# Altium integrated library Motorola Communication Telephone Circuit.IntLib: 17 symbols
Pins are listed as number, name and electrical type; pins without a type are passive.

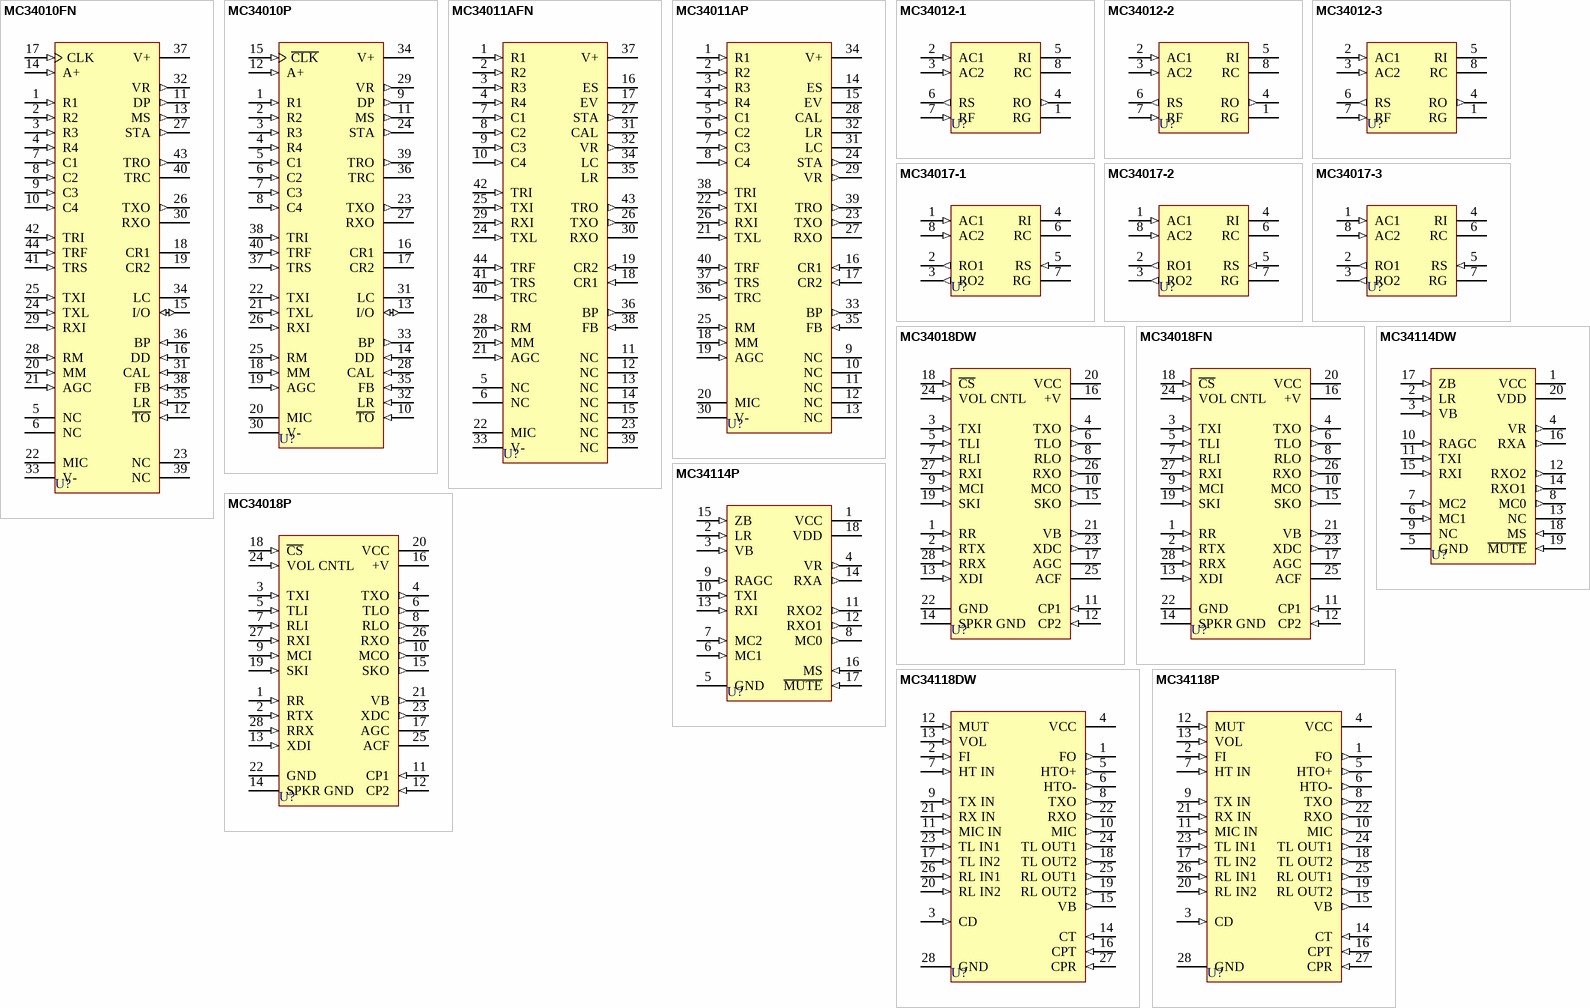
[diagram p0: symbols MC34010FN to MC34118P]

## MC34010FN
designator U?
Electronic Telephone Circuit
footprint 777-02_N (Leaded Chip Carrier, 44-Leads, Body 16.6x16.6mm, Pitch 1.27mm, IPC Medium Density)
footprint 777-02_L (Leaded Chip Carrier, 44-Leads, Body 16.6x16.6mm, Pitch 1.27mm, IPC High Density)
footprint 777-02_M (Leaded Chip Carrier, 44-Leads, Body 16.6x16.6mm, Pitch 1.27mm, IPC Low Density)
3D model MC34010-777-02 (44-Pin Plastic Leaded Chip Carrier 1.27 mm Pitch)
pins: 1 R1 (in), 2 R2 (in), 3 R3 (in), 4 R4 (in), 5 NC, 6 NC, 7 C1 (in), 8 C2 (in), 9 C3 (in), 10 C4 (in), 11 DP (out), 12 ~{TO} (in), 13 MS (out), 14 A+ (in), 15 I/O (io), 16 DD (in), 17 CLK (in), 18 CR1, 19 CR2, 20 MM (in), 21 AGC (in), 22 MIC (power), 23 NC, 24 TXL (in), 25 TXI (in), 26 TXO (out), 27 STA (out), 28 RM (in), 29 RXI (in), 30 RXO (oc), 31 CAL (in), 32 VR (out), 33 V- (power), 34 LC, 35 LR (in), 36 BP (in), 37 V+ (power), 38 FB (in), 39 NC, 40 TRC, 41 TRS (in), 42 TRI (in), 43 TRO (out), 44 TRF (in)

## MC34010P
designator U?
Electronic Telephone Circuit
footprint 711-03 (DIP; 40 Leads; Row Spacing 15.24 mm; Pitch 2.54 mm)
3D model 711-03 (DIP; 40 Leads; Row Spacing 15.24 mm; Pitch 2.54 mm)
pins: 1 R1 (in), 2 R2 (in), 3 R3 (in), 4 R4 (in), 5 C1 (in), 6 C2 (in), 7 C3 (in), 8 C4 (in), 9 DP (out), 10 ~{TO} (in), 11 MS (out), 12 A+ (in), 13 I/O (io), 14 DD (in), 15 ~{CLK} (in), 16 CR1, 17 CR2, 18 MM (in), 19 AGC (in), 20 MIC (power), 21 TXL (in), 22 TXI (in), 23 TXO (out), 24 STA (out), 25 RM (in), 26 RXI (in), 27 RXO (oc), 28 CAL (in), 29 VR (out), 30 V- (power), 31 LC, 32 LR (in), 33 BP (out), 34 V+ (power), 35 FB (in), 36 TRC, 37 TRS (in), 38 TRI (in), 39 TRO (out), 40 TRF (in)

## MC34011AFN
designator U?
Electronic Telephone Circuit
footprint 777-02_N (Leaded Chip Carrier, 44-Leads, Body 16.6x16.6mm, Pitch 1.27mm, IPC Medium Density)
footprint 777-02_L (Leaded Chip Carrier, 44-Leads, Body 16.6x16.6mm, Pitch 1.27mm, IPC High Density)
footprint 777-02_M (Leaded Chip Carrier, 44-Leads, Body 16.6x16.6mm, Pitch 1.27mm, IPC Low Density)
3D model MC34011A-777-02 (44-Pin Plastic Leaded Chip Carrier 1.27 mm Pitch)
pins: 1 R1 (in), 2 R2 (in), 3 R3 (in), 4 R4 (in), 5 NC, 6 NC, 7 C1 (in), 8 C2 (in), 9 C3 (in), 10 C4 (in), 11 NC, 12 NC, 13 NC, 14 NC, 15 NC, 16 ES, 17 EV, 18 CR1 (in), 19 CR2 (in), 20 MM (in), 21 AGC (in), 22 MIC (power), 23 NC, 24 TXL (in), 25 TXI (in), 26 TXO (out), 27 STA (out), 28 RM (in), 29 RXI (in), 30 RXO (oc), 31 CAL, 32 VR (out), 33 V- (power), 34 LC, 35 LR, 36 BP (out), 37 V+ (power), 38 FB (in), 39 NC, 40 TRC (in), 41 TRS (in), 42 TRI (in), 43 TRO (out), 44 TRF (in)

## MC34011AP
designator U?
Electronic Telephone Circuit
footprint 711-03 (DIP; 40 Leads; Row Spacing 15.24 mm; Pitch 2.54 mm)
3D model 711-03 (DIP; 40 Leads; Row Spacing 15.24 mm; Pitch 2.54 mm)
pins: 1 R1 (in), 2 R2 (in), 3 R3 (in), 4 R4 (in), 5 C1 (in), 6 C2 (in), 7 C3 (in), 8 C4 (in), 9 NC, 10 NC, 11 NC, 12 NC, 13 NC, 14 ES, 15 EV, 16 CR1 (in), 17 CR2 (in), 18 MM (in), 19 AGC (in), 20 MIC (power), 21 TXL (in), 22 TXI (in), 23 TXO (out), 24 STA (out), 25 RM (in), 26 RXI (in), 27 RXO (oc), 28 CAL, 29 VR (out), 30 V- (power), 31 LC, 32 LR, 33 BP (out), 34 V+ (power), 35 FB (in), 36 TRC (in), 37 TRS (in), 38 TRI (in), 39 TRO (out), 40 TRF (in)

## MC34012-1
designator U?
Telephone Tone Ringer
footprint 626-05 (DIP; 8 Leads; Row Spacing 7.62 mm; Pitch 2.54 mm)
3D model 626-05 (DIP; 8 Leads; Row Spacing 7.62 mm; Pitch 2.54 mm)
pins: 1 RG (power), 2 AC1 (in), 3 AC2 (in), 4 RO (out), 5 RI (power), 6 RS (out), 7 RF (in), 8 RC

## MC34012-2
designator U?
Telephone Tone Ringer
footprint 626-05 (DIP; 8 Leads; Row Spacing 7.62 mm; Pitch 2.54 mm)
3D model 626-05 (DIP; 8 Leads; Row Spacing 7.62 mm; Pitch 2.54 mm)
pins: 1 RG (power), 2 AC1 (in), 3 AC2 (in), 4 RO (out), 5 RI (power), 6 RS (out), 7 RF (in), 8 RC

## MC34012-3
designator U?
Telephone Tone Ringer
footprint 626-05 (DIP; 8 Leads; Row Spacing 7.62 mm; Pitch 2.54 mm)
3D model 626-05 (DIP; 8 Leads; Row Spacing 7.62 mm; Pitch 2.54 mm)
pins: 1 RG (power), 2 AC1 (in), 3 AC2 (in), 4 RO (out), 5 RI (power), 6 RS (out), 7 RF (in), 8 RC

## MC34017-1
designator U?
Telephone Tone Ringer
footprint 626-04 (DIP; 8 Leads; Row Spacing 7.62 mm; Pitch 2.54 mm)
3D model 626-05 (DIP; 8 Leads; Row Spacing 7.62 mm; Pitch 2.54 mm)
pins: 1 AC1 (in), 2 RO1 (out), 3 RO2 (out), 4 RI (power), 5 RS (in), 6 RC, 7 RG (power), 8 AC2 (in)

## MC34017-2
designator U?
Telephone Tone Ringer
footprint 626-04 (DIP; 8 Leads; Row Spacing 7.62 mm; Pitch 2.54 mm)
3D model 626-05 (DIP; 8 Leads; Row Spacing 7.62 mm; Pitch 2.54 mm)
pins: 1 AC1 (in), 2 RO1 (out), 3 RO2 (out), 4 RI (power), 5 RS (in), 6 RC, 7 RG (power), 8 AC2 (in)

## MC34017-3
designator U?
Telephone Tone Ringer
footprint 626-04 (DIP; 8 Leads; Row Spacing 7.62 mm; Pitch 2.54 mm)
3D model 626-05 (DIP; 8 Leads; Row Spacing 7.62 mm; Pitch 2.54 mm)
pins: 1 AC1 (in), 2 RO1 (out), 3 RO2 (out), 4 RI (power), 5 RS (in), 6 RC, 7 RG (power), 8 AC2 (in)

## MC34018DW
designator U?
Voice-Switched Speaker Phone Circuit
footprint 751F-03_N (SOIC, 28-Leads, Body 17.9x7.5mm, Pitch 1.27mm, IPC Medium Density)
footprint 751F-03_L (SOIC, 28-Leads, Body 17.9x7.5mm, Pitch 1.27mm, IPC High Density)
footprint 751F-03_M (SOIC, 28-Leads, Body 17.9x7.5mm, Pitch 1.27mm, IPC Low Density)
3D model 751F-03 (28-Pin Small Outline Integrated Circuit 1.27 mm Pitch)
pins: 1 RR (in), 2 RTX (in), 3 TXI (in), 4 TXO (out), 5 TLI (in), 6 TLO (out), 7 RLI (in), 8 RLO (out), 9 MCI (in), 10 MCO (out), 11 CP1 (in), 12 CP2 (in), 13 XDI (in), 14 SPKR GND (power), 15 SKO (out), 16 +V (power), 17 AGC, 18 ~{CS} (in), 19 SKI (in), 20 VCC (power), 21 VB (out), 22 GND (power), 23 XDC (out), 24 VOL CNTL (in), 25 ACF, 26 RXO (out), 27 RXI (in), 28 RRX (in)

## MC34018FN
designator U?
Voice-Switched Speaker Phone Circuit
footprint 776-02_N (Leaded Chip Carrier, 28-Leads, Body 11.5x11.5mm, Pitch 1.27mm, IPC Medium Density)
footprint 776-02_L (Leaded Chip Carrier, 28-Leads, Body 11.5x11.5mm, Pitch 1.27mm, IPC High Density)
footprint 776-02_M (Leaded Chip Carrier, 28-Leads, Body 11.5x11.5mm, Pitch 1.27mm, IPC Low Density)
3D model MC34018-776-02 (28-Pin Leaded Chip Carrier 1.27 mm Pitch)
pins: 1 RR (in), 2 RTX (in), 3 TXI (in), 4 TXO (out), 5 TLI (in), 6 TLO (out), 7 RLI (in), 8 RLO (out), 9 MCI (in), 10 MCO (out), 11 CP1 (in), 12 CP2 (in), 13 XDI (in), 14 SPKR GND (power), 15 SKO (out), 16 +V (power), 17 AGC, 18 ~{CS} (in), 19 SKI (in), 20 VCC (power), 21 VB (out), 22 GND (power), 23 XDC (out), 24 VOL CNTL (in), 25 ACF, 26 RXO (out), 27 RXI (in), 28 RRX (in)

## MC34018P
designator U?
Voice-Switched Speaker Phone Circuit
footprint 710-02 (DIP; 28 Leads; Row Spacing 15.24 mm; Pitch 2.54 mm)
3D model 710-02 (DIP; 28 Leads; Row Spacing 15.24 mm; Pitch 2.54 mm)
pins: 1 RR (in), 2 RTX (in), 3 TXI (in), 4 TXO (out), 5 TLI (in), 6 TLO (out), 7 RLI (in), 8 RLO (out), 9 MCI (in), 10 MCO (out), 11 CP1 (in), 12 CP2 (in), 13 XDI (in), 14 SPKR GND (power), 15 SKO (out), 16 +V (power), 17 AGC, 18 ~{CS} (in), 19 SKI (in), 20 VCC (power), 21 VB (out), 22 GND (power), 23 XDC (out), 24 VOL CNTL (in), 25 ACF, 26 RXO (out), 27 RXI (in), 28 RRX (in)

## MC34114DW
designator U?
Telephone Speech Network with Dialer Interface
footprint 751D-03_N (SOIC, 20-Leads, Body 12.8x7.5mm, Pitch 1.27mm, IPC Medium Density)
footprint 751D-03_L (SOIC, 20-Leads, Body 12.8x7.5mm, Pitch 1.27mm, IPC High Density)
footprint 751D-03_M (SOIC, 20-Leads, Body 12.8x7.5mm, Pitch 1.27mm, IPC Low Density)
3D model 751D-03 (20-Pin Small Outline Integrated Circuit 1.27 mm Pitch)
pins: 1 VCC (power), 2 LR (in), 3 VB (in), 4 VR (out), 5 GND (power), 6 MC1 (in), 7 MC2 (in), 8 MC0 (out), 9 NC, 10 RAGC (in), 11 TXI (in), 12 RXO2 (out), 13 NC, 14 RXO1 (out), 15 RXI (in), 16 RXA (out), 17 ZB (in), 18 MS (in), 19 ~{MUTE} (in), 20 VDD (power)

## MC34114P
designator U?
Telephone Speech Network with Dialer Interface
footprint 707-02 (DIP; 18 Leads; Row Spacing 7.62 mm; Pitch 2.54 mm)
3D model 707-02 (DIP; 18 Leads; Row Spacing 7.62 mm; Pitch 2.54 mm)
pins: 1 VCC (power), 2 LR (in), 3 VB (in), 4 VR (out), 5 GND (power), 6 MC1 (in), 7 MC2 (in), 8 MC0 (out), 9 RAGC (in), 10 TXI (in), 11 RXO2 (out), 12 RXO1 (out), 13 RXI (in), 14 RXA (out), 15 ZB (in), 16 MS (in), 17 ~{MUTE} (in), 18 VDD (power)

## MC34118DW
designator U?
Voice-Switched Speaker Phone Circuit
footprint 751F-03_N (SOIC, 28-Leads, Body 17.9x7.5mm, Pitch 1.27mm, IPC Medium Density)
footprint 751F-03_L (SOIC, 28-Leads, Body 17.9x7.5mm, Pitch 1.27mm, IPC High Density)
footprint 751F-03_M (SOIC, 28-Leads, Body 17.9x7.5mm, Pitch 1.27mm, IPC Low Density)
3D model 751F-03 (28-Pin Small Outline Integrated Circuit 1.27 mm Pitch)
pins: 1 FO (out), 2 FI (in), 3 CD (in), 4 VCC (power), 5 HTO+ (out), 6 HTO- (out), 7 HT IN (in), 8 TXO (out), 9 TX IN (in), 10 MIC (out), 11 MIC IN (in), 12 MUT (in), 13 VOL (in), 14 CT (in), 15 VB (out), 16 CPT (in), 17 TL IN2 (in), 18 TL OUT2 (out), 19 RL OUT2 (out), 20 RL IN2 (in), 21 RX IN (in), 22 RXO (out), 23 TL IN1 (in), 24 TL OUT1 (out), 25 RL OUT1 (out), 26 RL IN1 (in), 27 CPR (in), 28 GND (power)

## MC34118P
designator U?
Voice-Switched Speaker Phone Circuit
footprint 710-02 (DIP; 28 Leads; Row Spacing 15.24 mm; Pitch 2.54 mm)
3D model 710-02 (DIP; 28 Leads; Row Spacing 15.24 mm; Pitch 2.54 mm)
pins: 1 FO (out), 2 FI (in), 3 CD (in), 4 VCC (power), 5 HTO+ (out), 6 HTO- (out), 7 HT IN (in), 8 TXO (out), 9 TX IN (in), 10 MIC (out), 11 MIC IN (in), 12 MUT (in), 13 VOL (in), 14 CT (in), 15 VB (out), 16 CPT (in), 17 TL IN2 (in), 18 TL OUT2 (out), 19 RL OUT2 (out), 20 RL IN2 (in), 21 RX IN (in), 22 RXO (out), 23 TL IN1 (in), 24 TL OUT1 (out), 25 RL OUT1 (out), 26 RL IN1 (in), 27 CPR (in), 28 GND (power)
